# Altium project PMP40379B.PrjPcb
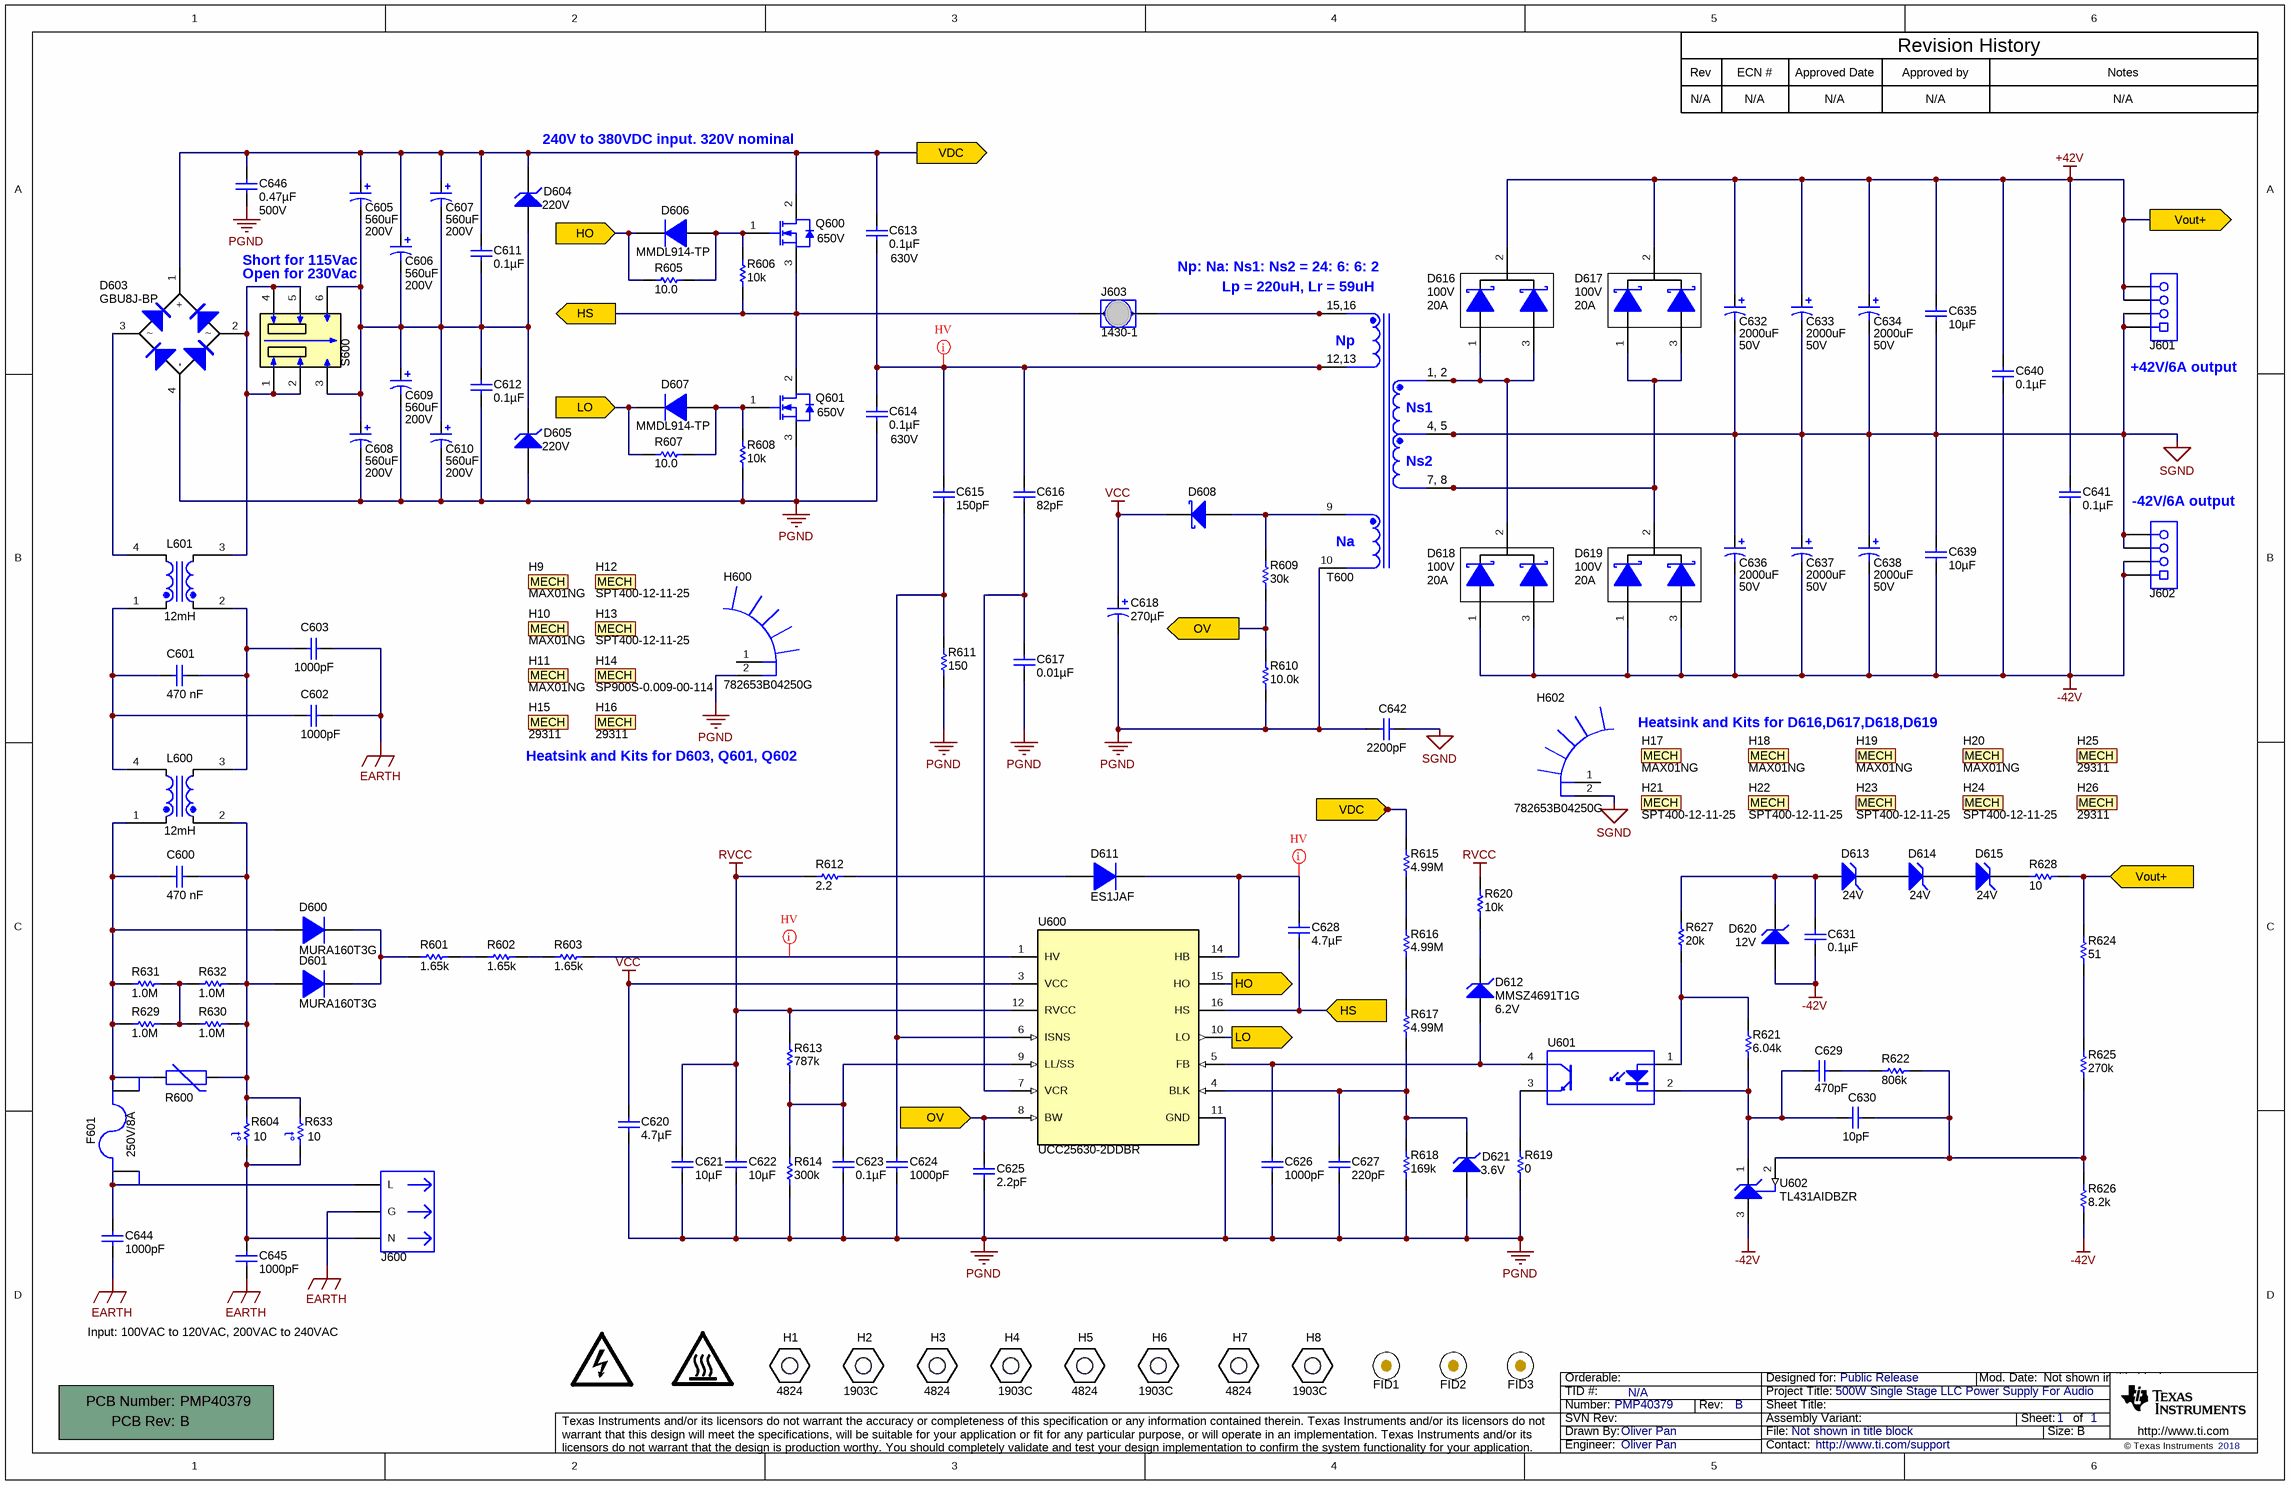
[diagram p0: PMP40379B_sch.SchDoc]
TID: N/A; TechSupport: http://www.ti.com/support; SCH_Rev: B; PRJ_Title: 500W Single Stage LLC Power Supply For Audio; PRJ_Number: PMP40379; PRJ_Engineer: Oliver Pan; PRJ_Customer: Public Release; PCB_Rev: B; PCB_Layout: Oliver Pan; Date: 1222; CopyrightYear: 2018
1 sheet, 146 parts. Net scope: flat (ports and power ports of the same name join across sheets).
Board file: PMP40379B_pcb.PcbDoc

## Sheet PMP40379B_sch.SchDoc
size 431 x 279 mm; Date: Not shown in title block; ApprovedBy: Not shown in title block; CheckedBy: Not shown in title block; Author: Not shown in title block; CompanyName: Not shown in title block; DrawnBy: Oliver Pan; Engineer: Not shown in title block; Organization: Not shown in title block; Address1: Not shown in title block; Address2: Not shown in title block; Address3: Not shown in title block; Address4: Not shown in title block; DocumentNumber: 1; Revision: Use project parameter SCH_Rev; SheetNumber: 1; SheetTotal: 1; PageSetup: Record=PageOptions¦CenterHorizontal=True¦CenterVertical=True¦PrintScale=1.00¦XCorrection=1.00¦YCorrection=1.00¦PrintKind=0¦BorderSize=5000000¦LeftOffset=0¦BottomOffset=0¦Orientation=2¦PaperLength=1000¦PaperWidth=1000¦Scale=100¦PaperSource=15¦PrintQuality=600¦MediaType=1¦DitherType=10¦PaperKind=Letter¦PrintScaleMode=1

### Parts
!PCB600  Printed Circuit Board  (value not drawn)  (mechanical)
C600  value 470 nF  [WCAP-FTX2_18x8x14_CS]  (hidden comment: 275V AC, 470 nF)
C601  value 470 nF  [WCAP-FTX2_18x8x14_CS]  (hidden comment: 275V AC, 470 nF)
C602  ValueDisplayed: 1000pF  [CD45_700x600x1100]  (hidden comment: CD45-E2GA102M-NKA)
C603  ValueDisplayed: 1000pF  [CD45_700x600x1100]  (hidden comment: CD45-E2GA102M-NKA)
C605  value 560uF  Value2: 200V  [CAPPR7.5-18x40]  (hidden comment: EPAG201ELL561MM45S)
C606  value 560uF  Value2: 200V  [CAPPR7.5-18x40]  (hidden comment: EPAG201ELL561MM45S)
C607  value 560uF  Value2: 200V  [CAPPR7.5-18x40]  (hidden comment: EPAG201ELL561MM45S)
C608  value 560uF  Value2: 200V  [CAPPR7.5-18x40]  (hidden comment: EPAG201ELL561MM45S)
C609  value 560uF  Value2: 200V  [CAPPR7.5-18x40]  (hidden comment: EPAG201ELL561MM45S)
C610  value 560uF  Value2: 200V  [CAPPR7.5-18x40]  (hidden comment: EPAG201ELL561MM45S)
C611  ValueDisplayed: 0.1µF  [1206_180]  (hidden comment: GRM31CR72E104KW03L)
C612  ValueDisplayed: 0.1µF  [1206_180]  (hidden comment: GRM31CR72E104KW03L)
C613  ValueDisplayed: 0.1µF  Value2: 630V  [CAPRR1500W80L1800T770H1210]  (hidden comment: ECW-F6104JL)
C614  ValueDisplayed: 0.1µF  Value2: 630V  [CAPRR1500W80L1800T770H1210]  (hidden comment: ECW-F6104JL)
C615  ValueDisplayed: 150pF  [1206]  (hidden comment: GRM31A5C2J151JW01D)
C616  ValueDisplayed: 82pF  [1206]  (hidden comment: GRM31A5C2J820JW01D)
C617  ValueDisplayed: 0.01µF  [0603]  (hidden comment: GRM188R71C103KA01D)
C618  ValueDisplayed: 270µF  [Chemi-Con_800x2000]  (hidden comment: EKZE350ELL271MH20D)
C620  ValueDisplayed: 4.7µF  [1206]  (hidden comment: C3216X7R1V475K085AC)
C621  ValueDisplayed: 10µF  [0805]  (hidden comment: GRM21BC71C106KE11L)
C622  ValueDisplayed: 10µF  [0805]  (hidden comment: GRM21BC71C106KE11L)
C623  ValueDisplayed: 0.1µF  [0603]  (hidden comment: C1608X7R1H104K080AA)
C624  ValueDisplayed: 1000pF  [0603]  (hidden comment: GRM1885C1H102JA01D)
C625  ValueDisplayed: 2.2pF  [0603]  (hidden comment: 06035A2R2CAT2A)
C626  ValueDisplayed: 1000pF  [0603]  (hidden comment: GRM1885C2A102JA01D)
C627  ValueDisplayed: 220pF  [0603]  (hidden comment: GRM188R71H221KA01D)
C628  ValueDisplayed: 4.7µF  [1206_180]  (hidden comment: GRM31CR71C475KA01L)
C629  ValueDisplayed: 470pF  [0603]  (hidden comment: C0603X471K5RACTU)
C630  ValueDisplayed: 10pF  [0603]  (hidden comment: 06035A100JAT2A)
C631  ValueDisplayed: 0.1µF  [0603]  (hidden comment: 06033C104JAT2A)
C632  value 2000uF  Value2: 50V  [Chemi-Con_1450x2000]  (hidden comment: EGXF500ELL202MU40S)
C633  value 2000uF  Value2: 50V  [Chemi-Con_1450x2000]  (hidden comment: EGXF500ELL202MU40S)
C634  value 2000uF  Value2: 50V  [Chemi-Con_1450x2000]  (hidden comment: EGXF500ELL202MU40S)
C635  ValueDisplayed: 10µF  [1206_180]  (hidden comment: C3216X5R1H106K160AB)
C636  value 2000uF  Value2: 50V  [Chemi-Con_1450x2000]  (hidden comment: EGXF500ELL202MU40S)
C637  value 2000uF  Value2: 50V  [Chemi-Con_1450x2000]  (hidden comment: EGXF500ELL202MU40S)
C638  value 2000uF  Value2: 50V  [Chemi-Con_1450x2000]  (hidden comment: EGXF500ELL202MU40S)
C639  ValueDisplayed: 10µF  [1206_180]  (hidden comment: C3216X5R1H106K160AB)
C640  ValueDisplayed: 0.1µF  [1206]  (hidden comment: 12061C104JAT2A)
C641  ValueDisplayed: 0.1µF  [1206]  (hidden comment: 12061C104JAT2A)
C642  ValueDisplayed: 2200pF  [AY2_950x500_Straight]  (hidden comment: AY2222M35Y5US63L7)
C644  ValueDisplayed: 1000pF  [CD45_700x600x1100]  (hidden comment: CD45-E2GA102M-NKA)
C645  ValueDisplayed: 1000pF  [CD45_700x600x1100]  (hidden comment: CD45-E2GA102M-NKA)
C646  ValueDisplayed: 0.47µF  Value2: 500V  [1812_254]  (hidden comment: 1812Y5000474KXTWS2)
D600  MURA160T3G  [SMA]
D601  MURA160T3G  [SMA]
D603  GBU8J-BP  [GBU]
D604  value 220V  [SMB]  (hidden comment: P6SMB220A-E3/52)
D605  value 220V  [SMB]  (hidden comment: P6SMB220A-E3/52)
D606  MMDL914-TP  [SOD-323]
D607  MMDL914-TP  [SOD-323]
D608  STPS160UY  [SMB]  (value not drawn)
D611  ES1JAF  [SMAF]
D612  MMSZ4691T1G  value 6.2V  [SOD-123]
D613  value 24V  [SOD-123]  (hidden comment: MMSZ5252B-7-F)
D614  value 24V  [SOD-123]  (hidden comment: MMSZ5252B-7-F)
D615  value 24V  [SOD-123]  (hidden comment: MMSZ5252B-7-F)
D616  value 100V  Value1: 20A  [TO-220AB]  (hidden comment: STPS41H100CTY)
D617  value 100V  Value1: 20A  [TO-220AB]  (hidden comment: STPS41H100CTY)
D618  value 100V  Value1: 20A  [TO-220AB]  (hidden comment: STPS41H100CTY)
D619  value 100V  Value1: 20A  [TO-220AB]  (hidden comment: STPS41H100CTY)
D620  value 12V  [SOD-123]  (hidden comment: MMSZ5242B-7-F)
D621  value 3.6V  [SOD-123]  (hidden comment: MMSZ5227B-7-F)
F601  value 250V/8A  (hidden comment: 5HF 8-R)  (mechanical)
FID1  Fiducial  [Fiducial10-20]  (value not drawn)
FID2  Fiducial  [Fiducial10-20]  (value not drawn)
FID3  Fiducial  [Fiducial10-20]  (value not drawn)
H1  4824  [KEYSTONE_4824]
H2  1903C  [KEYSTONE_1903C]
H3  4824  [KEYSTONE_4824]
H4  1903C  [KEYSTONE_1903C]
H5  4824  [KEYSTONE_4824]
H6  1903C  [KEYSTONE_1903C]
H7  4824  [KEYSTONE_4824]
H8  1903C  [KEYSTONE_1903C]
H9  MAX01NG  (mechanical)
H10  MAX01NG  (mechanical)
H11  MAX01NG  (mechanical)
H12  SPT400-12-11-25  (mechanical)
H13  SPT400-12-11-25  (mechanical)
H14  SP900S-0.009-00-114  (mechanical)
H15  29311  (mechanical)
H16  29311  (mechanical)
H17  MAX01NG  (mechanical)
H18  MAX01NG  (mechanical)
H19  MAX01NG  (mechanical)
H20  MAX01NG  (mechanical)
H21  SPT400-12-11-25  (mechanical)
H22  SPT400-12-11-25  (mechanical)
H23  SPT400-12-11-25  (mechanical)
H24  SPT400-12-11-25  (mechanical)
H25  29311  (mechanical)
H26  29311  (mechanical)
H600  782653B04250G  [HEATSINK_782653B04250G]
H602  782653B04250G  [HEATSINK_782653B04250G]
J600  703W-00/54  [CONN_QUALTEK-703W-0054]  (value not drawn)
J601  ED120/4DS  [On-Shore_ED120_4DS]  (value not drawn)
J602  ED120/4DS  [On-Shore_ED120_4DS]  (value not drawn)
J603  1430-1  [Keystone_1430-1]
L600  value 12mH  [WE-CMBNC_Type XL_7448051012]  (hidden comment: 7448051012)
L601  value 12mH  [WE-CMBNC_Type XL_7448051012]  (hidden comment: 7448051012)
Logo1  DANGER HIGH VOLTAGE  [IEC_HighVoltage_Medium]  (value not drawn)  (no BOM)
Logo2  CAUTION HOT SURFACE  [IEC_HotSurface_Small]  (value not drawn)  (no BOM)
Q600  value 650V  [TO-220FP]  (hidden comment: IPA65R190CFD)
Q601  value 650V  [TO-220FP]  (hidden comment: IPA65R190CFD)
R600  S10K275E2  [VAR_S10K275E2]  (value not drawn)
R601  ValueDisplayed: 1.65k  [1206]  (hidden comment: CRCW12061K65FKEA)
R602  ValueDisplayed: 1.65k  [1206]  (hidden comment: CRCW12061K65FKEA)
R603  ValueDisplayed: 1.65k  [1206]  (hidden comment: CRCW12061K65FKEA)
R604  value 10  [SPNL20]  (hidden comment: B57364S0100M051)
R605  ValueDisplayed: 10.0  [0603]  (hidden comment: CRCW060310R0FKEA)
R606  ValueDisplayed: 10k  [0603]  (hidden comment: RC0603JR-0710KL)
R607  ValueDisplayed: 10.0  [0603]  (hidden comment: CRCW060310R0FKEA)
R608  ValueDisplayed: 10k  [0603]  (hidden comment: RC0603JR-0710KL)
R609  ValueDisplayed: 30k  [0603]  (hidden comment: CRCW060330K0JNEA)
R610  ValueDisplayed: 10.0k  [0603]  (hidden comment: CRCW060310K0FKEA)
R611  ValueDisplayed: 150  [1206]  (hidden comment: RC1206FR-07150RL)
R612  ValueDisplayed: 2.2  [0603]  (hidden comment: CRCW06032R20JNEA)
R613  ValueDisplayed: 787k  [0603]  (hidden comment: CRCW0603787KFKEA)
R614  ValueDisplayed: 300k  [0603]  (hidden comment: CRCW0603300KJNEA)
R615  ValueDisplayed: 4.99M  [1206]  (hidden comment: CRCW12064M99FKEA)
R616  ValueDisplayed: 4.99M  [1206]  (hidden comment: CRCW12064M99FKEA)
R617  ValueDisplayed: 4.99M  [1206]  (hidden comment: CRCW12064M99FKEA)
R618  ValueDisplayed: 169k  [0603]  (hidden comment: RC0603FR-07169KL)
R619  ValueDisplayed: 0  [0603]  (hidden comment: CRCW06030000Z0EA)
R620  ValueDisplayed: 10k  [0603]  (hidden comment: CRCW060310K0JNEA)
R621  ValueDisplayed: 6.04k  [0603]  (hidden comment: CRCW06036K04FKEA)
R622  ValueDisplayed: 806k  [0603]  (hidden comment: CRCW0603806KFKEA)
R624  ValueDisplayed: 51  [0603]  (hidden comment: CRCW060351R0JNEA)
R625  ValueDisplayed: 270k  [0603]  (hidden comment: CRCW0603270KJNEA)
R626  ValueDisplayed: 8.2k  [0603]  (hidden comment: CRCW06038K20JNEA)
R627  ValueDisplayed: 20k  [0603]  (hidden comment: CRCW060320K0JNEA)
R628  ValueDisplayed: 10  [0603]  (hidden comment: CRCW060310R0JNEA)
R629  ValueDisplayed: 1.0M  [1206]  (hidden comment: CRCW12061M00JNEA)
R630  ValueDisplayed: 1.0M  [1206]  (hidden comment: CRCW12061M00JNEA)
R631  ValueDisplayed: 1.0M  [1206]  (hidden comment: CRCW12061M00JNEA)
R632  ValueDisplayed: 1.0M  [1206]  (hidden comment: CRCW12061M00JNEA)
R633  value 10  [SPNL20]  (hidden comment: B57364S0100M051)
S600  V80212MS02Q  [SW_V80212MS02Q]  (value not drawn)
T600  750343844  [WE-LLCR_ETD44]  (value not drawn)
U600  UCC25630-2DDBR  [DDB0014A]
U601  VO618A  [DIP-4]  (value not drawn)
U602  TL431AIDBZR  [DBZ0003A_N]
XF1  0751.0052  [SCHURTER_0751_0052]  (value not drawn)
XF2  0751.0052  [SCHURTER_0751_0052]  (value not drawn)

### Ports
HO, HS, LO, OV, VDC, Vout+

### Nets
+42V: C632.1(+) C633.1(+) C634.1(+) C635.1 C640.1 C641.1 D616.2(K) D617.2(K) J601.3 J601.4 R624.2 R628.1 ; port Vout+
-42V: C631.2 C636.2(-) C637.2(-) C638.2(-) C639.2 C640.2 C641.2 D618.1(A) D618.3(A) D619.1(A) D619.3(A) D620.2(A) J602.1 J602.2 R626.1 U602.3(ANODE)
EARTH: C602.2 C603.2 C644.2 C645.1 J600.3(G)
PGND: C608.2(-) C609.2(-) C610.2(-) C612.2 C614.2 C617.2 C618.2(-) C620.1 C621.2 C622.2 C623.2 C624.1 C625.2 C626.2 C627.2 C642.2 C646.2 D603.4(-) D605.2(A) D621.2(A) H600.2 Q601.3(S) R608.1 R610.1 R611.1 R614.1 R618.1 R619.1 T600.10 U600.11(GND)
RVCC: C621.1 C622.1 R612.1 R613.2 R620.2 U600.12(RVCC)
SGND: C632.2(-) C633.2(-) C634.2(-) C635.2 C636.1(+) C637.1(+) C638.1(+) C639.1 C642.1 H602.2 J601.1 J601.2 J602.3 J602.4 T600.4 T600.5
VCC: C618.1(+) C620.2 D608.1(K) U600.3(VCC)
HO: D606.1(K) R605.1 U600.15(HO) ; port HO
HS: C628.2 J603.1 Q600.3(S) Q601.2(D) R606.1 U600.16(HS) ; port HS
LO: D607.1(K) R607.1 U600.10(LO) ; port LO
OV: C625.1 R609.1 R610.2 U600.8(BW) ; port OV
VDC: C605.1(+) C606.1(+) C607.1(+) C611.1 C613.1 C646.1 D603.1(+) D604.1(K) Q600.2(D) R615.2 ; port VDC
NetC600_1: C600.1 D600.2(A) L600.1 R600.1 R629.2 R631.2 XF2.1 XF2.2
NetC600_2: C600.2 D601.2(A) L600.2 R600.2 R604.1 R630.1 R632.1 R633.1
NetC601_1: C601.1 C602.1 L600.4 L601.1
NetC601_2: C601.2 C603.1 L600.3 L601.2
NetC605_2: C605.2(-) C606.2(-) C607.2(-) C608.1(+) C609.1(+) C610.1(+) C611.2 C612.1 D604.2(A) D605.1(K) S600.3 S600.6
NetC613_2: C613.2 C614.1 C615.1 C616.1 T600.12 T600.13
NetC615_2: C615.2 C624.2 R611.2 U600.6(ISNS)
NetC616_2: C616.2 C617.1 U600.7(VCR)
NetC623_1: C623.1 R613.1 R614.2 U600.9(LL/SS)
NetC626_1: C626.1 D612.2(A) U600.5(FB) U601.4(C)
NetC627_1: C627.1 D621.1(K) R617.1 R618.2 U600.4(BLK)
NetC628_1: C628.1 D611.1(K) U600.14(HB)
NetC629_1: C629.1 R622.1
NetC629_2: C629.2 C630.2 R621.1 U601.2(K) U602.1(CATHODE)
NetC630_1: C630.1 R622.2 R625.1 R626.2 U602.2(REF)
NetC631_1: C631.1 D613.2(A) D620.1(K) R627.2
NetC644_1: C644.1 J600.1(L) XF1.1 XF1.2
NetC645_2: C645.2 J600.2(N) R604.2 R633.2
NetD600_1: D600.1(K) D601.1(K) R601.2
NetD603_2: D603.2 L601.3 S600.1 S600.2(C) S600.4 S600.5(C)
NetD603_3: D603.3 L601.4
NetD606_2: D606.2(A) Q600.1(G) R605.2 R606.2
NetD607_2: D607.2(A) Q601.1(G) R607.2 R608.2
NetD608_2: D608.2(A) R609.2 T600.9
NetD611_2: D611.2(A) R612.2
NetD612_1: D612.1(K) R620.1
NetD613_1: D613.1(K) D614.2(A)
NetD614_1: D614.1(K) D615.2(A)
NetD615_1: D615.1(K) R628.2
NetD616_1: D616.1(A) D616.3(A) D618.2(K) T600.1 T600.2
NetD617_1: D617.1(A) D617.3(A) D619.2(K) T600.7 T600.8
NetJ603_2: J603.2 T600.15 T600.16
NetR601_1: R601.1 R602.2
NetR602_1: R602.1 R603.2
NetR603_1: R603.1 U600.1(HV)
NetR615_1: R615.1 R616.2
NetR616_1: R616.1 R617.2
NetR619_2: R619.2 U601.3(E)
NetR621_2: R621.2 R627.1 U601.1(A)
NetR624_1: R624.1 R625.2
NetR629_1: R629.1 R630.2 R631.1 R632.2

Not connected (* = marked no-connect by the designer): H600 1; H602 1

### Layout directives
net class HV; rule Clearance Constraint [Clearance = 1.6mm]: NetC613_2
net class HV; rule Clearance Constraint [Clearance = 2.5mm]: NetC628_1
net class HV; rule Clearance Constraint [Clearance = 2mm]: NetR603_1

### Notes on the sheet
- Rev
- N/A
- ECN #
- Approved Date
- Approved by
- Revision History
- Notes
- 240V to 380VDC input. 320V nominal
- VDC start: 232 V
  VDC stop: 210 V
  VAC start: 82 V
  VAC stop: 75 V
- Short for 115Vac
- Open for 230Vac
- Np: Na: Ns1: Ns2 = 24: 6: 6: 2
- (near T600) Lp = 220uH, Lr = 59uH
- (near T600) Np
- (near J601) +42V/6A output
- (near T600) Ns1
- (near T600) Ns2
- (near J602) -42V/6A output
- (near T600) Na
- Heatsink and Kits for D603, Q601, Q602
- (near R610) Vout OVP: 45V
- Heatsink and Kits for D616,D617,D618,D619
- Input: 100VAC to 120VAC, 200VAC to 240VAC

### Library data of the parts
!PCB600 = PCB: Manufacturer: Any; PartNumber: PMP40379; SymbolCreator: a0412235
C600 C601 = 890324025039CS: WCAP-FTX2 Film Capacitors, 18x8x14mm, 275V AC, 470 nF; Manufacturer: Wurth Electronics; Rated Voltage: 275V AC
C602 C603 C644 C645 = CD45-E2GA102M-NKA: CAP, CERM, 1000 pF, X1 440 VAC/Y1 400 VAC, +/- 20%, E, D7xT6mm; Manufacturer: TDK; Polarized: N; CompType: Capacitor; Value: 1000pF; U/M: EA; Cap_F: 0.000000001; Tolerance_%: 20; TaMin_C: -25; TaMax_C: 125; Cap_Case: 7x6x11mm; SizeArea_mm2: 63.9; SizeAreaWB_mm2: 101.2; SizeX_mm: 10.65; SizeY_mm: 6; SizeZ_mm: 11; AEC Category: Q200; AC_Safety: X1Y1; VAC_X: 440; VAC_Y: 400
C605-C610 = Capacitor_Polarized: CAP ALUM 560UF 20% 200V RADIAL; Manufacturer: United Chemi-Con; Lifetime @ Temp.: 2000 Hrs @ 105°C; Polarization: Polar
C611 C612 = GRM31CR72E104KW03L: CAP, CERM, 0.1 µF, 250 V,+/- 10%, X7R, 1206; Manufacturer: MuRata; Polarized: N; CompType: Capacitor; Value: 0.1uF; U/M: EA; Cap_F: 0.0000001; Tolerance_%: 10; VDC_V: 250; Value2: 250V; TaMin_C: -55; TaMax_C: 125; Cap_Case: 1206; SizeAreaWB_mm2: 10.92; SizeArea_mm2: 5.12; SizeX_mm: 3.2; SizeY_mm: 1.6; SizeZ_mm: 1.8; AEC Category: Q200; Green_Lifecycle: Active; Green_REACh: Passed
C613 C614 = ECW-F6104JL: CAP, Film, 0.1 µF, 630 V,+/- 5%, TH; Manufacturer: Panasonic; Value: 0.1uF; Polarized: N; CompType: Capacitor; U/M: EA; Cap_F: 0.0000001; Tolerance_%: 5; VDC_V: 630; TaMin_C: -40; TaMax_C: 105; Cap_Case: Radial 18x7.7x13.6; AEC Category: Q200
C615 = GRM31A5C2J151JW01D: CAP, CERM, 150 pF, 630 V,+/- 5%, C0G/NP0, 1206; Manufacturer: MuRata; Polarized: N; CompType: Capacitor; Value: 150pF; U/M: EA; Cap_F: 0.00000000015; Tolerance_%: 5; VDC_V: 630; Value2: 630V; TaMin_C: -55; TaMax_C: 125; AEC Category: Q200; SizeArea_mm2: 5.12; SizeAreaWB_mm2: 10.92; SizeX_mm: 3.2; SizeY_mm: 1.6; SizeZ_mm: 1.35
C616 = GRM31A5C2J820JW01D: CAP, CERM, 82 pF, 630 V,+/- 5%, C0G/NP0, 1206; Manufacturer: MuRata; Tolerance_%: 5; VDC_V: 630; Value: 82pF; Polarized: N; CompType: Capacitor; U/M: EA; Cap_F: 0.000000000082; Value2: 630V; TaMin_C: -55; TaMax_C: 125; SizeArea_mm2: 5.12; SizeAreaWB_mm2: 10.92; SizeX_mm: 3.2; SizeY_mm: 1.6; SizeZ_mm: 1.35; AEC Category: Q200
C617 = GRM188R71C103KA01D: CAP, CERM, 0.01 µF, 16 V,+/- 10%, X7R, 0603; Manufacturer: MuRata; Polarized: N; CompType: Capacitor; Value: 0.01uF; U/M: EA; Cap_F: 0.00000001; Tolerance_%: 10; VDC_V: 16; Value2: 16V; TaMin_C: -55; TaMax_C: 125; SizeArea_mm2: 1.28; SizeAreaWB_mm2: 4.68; SizeX_mm: 1.6; SizeY_mm: 0.8; SizeZ_mm: 1; AEC Category: Q200; Green_Lifecycle: Active; Green_REACh: Passed
C618 = EKZE350ELL271MH20D: CAP, AL, 270 µF, 35 V, +/- 20%, TH; Manufacturer: Chemi-Con; Value: 270uF; Polarized: Y; CompType: Capacitor; U/M: EA; Cap_F: 0.00027; Tolerance_%: 20; VDC_V: 35; Value2: 35V; IRMS_A: 1.25; TaMin_C: -40; TaMax_C: 105; Cap_Case: 8x20; SizeAreaWB_mm2: 100; SizeArea_mm2: 64; SizeX_mm: 8; SizeZ_mm: 21.5; AEC Category: Q200; AEC Qualified: N
C620 = C3216X7R1V475K085AC: CAP, CERM, 4.7 µF, 35 V,+/- 10%, X7R, 1206; Manufacturer: TDK; Polarized: N; CompType: Capacitor; Value: 4.7uF; U/M: EA; Cap_F: 0.0000047; Tolerance_%: 10; ESR_ohm: 0.003785; Value1: 0.003785 ohm; VDC_V: 35; Value2: 35V; IRMS_A: 3.73011; TaMin_C: -55; TaMax_C: 125; AEC Category: Q200; SizeArea_mm2: 5.12; SizeAreaWB_mm2: 10.92; SizeX_mm: 3.2; SizeY_mm: 1.6; SizeZ_mm: 1.35
C621 C622 = GRM21BC71C106KE11L: CAP, CERM, 10 µF, 16 V,+/- 10%, X7S, 0805; Manufacturer: MuRata; Polarized: N; CompType: Capacitor; Value: 10uF; U/M: EA; Cap_F: 0.00001; Tolerance_%: 10; VDC_V: 16; Value2: 16V; TaMin_C: -55; TaMax_C: 125; AEC Category: Q200; SizeArea_mm2: 2.5; SizeAreaWB_mm2: 6.75; SizeX_mm: 2; SizeY_mm: 1.25; SizeZ_mm: 1.45
C623 = C1608X7R1H104K080AA: CAP, CERM, 0.1 µF, 50 V,+/- 10%, X7R, 0603; Manufacturer: TDK; Polarized: N; CompType: Capacitor; Value: 0.1uF; U/M: EA; Cap_F: 0.0000001; Tolerance_%: 10; ESR_ohm: 0.0296; Value1: 0.0296 ohm; VDC_V: 50; Value2: 50V; IRMS_A: 0.97199; TaMin_C: -55; TaMax_C: 125; AEC Category: Q200; SizeArea_mm2: 1.28; SizeAreaWB_mm2: 4.68; SizeX_mm: 1.6; SizeY_mm: 0.8; SizeZ_mm: 1; Green_Lifecycle: NRND; Green_REACh: Passed
C624 = GRM1885C1H102JA01D: CAP, CERM, 1000 pF, 50 V,+/- 5%, C0G/NP0, 0603; Manufacturer: MuRata; Polarized: N; CompType: Capacitor; Value: 1000pF; U/M: EA; Cap_F: 0.000000001; Tolerance_%: 5; VDC_V: 50; Value2: 50V; TaMin_C: -55; TaMax_C: 125; SizeArea_mm2: 1.28; SizeAreaWB_mm2: 4.68; SizeX_mm: 1.6; SizeY_mm: 0.8; SizeZ_mm: 1; AEC Category: Q200; Green_Lifecycle: Active; Green_REACh: Passed
C625 = 06035A2R2CAT2A: CAP, CERM, 2.2 pF, 50 V, +/- 11%, C0G/NP0, 0603; Manufacturer: AVX; Polarized: N; CompType: Capacitor; Value: 2.2pF; U/M: EA; Cap_F: 0.0000000000022; Tolerance_%: 11; ESR_ohm: 1.033; Value1: 1.033 ohm; VDC_V: 50; Value2: 50V; TaMin_C: -55; TaMax_C: 125; SizeArea_mm2: 1.28; SizeAreaWB_mm2: 4.68; SizeX_mm: 1.6; SizeY_mm: 0.8; SizeZ_mm: 1; AEC Category: Q200
C626 = GRM1885C2A102JA01D: CAP, CERM, 1000 pF, 100 V,+/- 5%, C0G/NP0, 0603; Manufacturer: MuRata; Polarized: N; CompType: Capacitor; Value: 1000pF; U/M: EA; Cap_F: 0.000000001; Tolerance_%: 5; VDC_V: 100; Value2: 100V; TaMin_C: -55; TaMax_C: 125; AEC Category: Q200; SizeArea_mm2: 1.28; SizeAreaWB_mm2: 4.68; SizeX_mm: 1.6; SizeY_mm: 0.8; SizeZ_mm: 1; Green_Lifecycle: Active; Green_REACh: Passed
C627 = GRM188R71H221KA01D: CAP, CERM, 220 pF, 50 V, +/- 10%, X7R, 0603; Manufacturer: MuRata; Polarized: N; CompType: Capacitor; Value: 220pF; U/M: EA; Cap_F: 0.00000000022; Tolerance_%: 10; Value1: Unknown; VDC_V: 50; Value2: 50V; TaMin_C: -55; TaMax_C: 125; AEC Category: Q200
C628 = GRM31CR71C475KA01L: CAP, CERM, 4.7 µF, 16 V,+/- 10%, X7R, 1206; Manufacturer: MuRata; Polarized: N; CompType: Capacitor; Value: 4.7uF; U/M: EA; Cap_F: 0.0000047; Tolerance_%: 10; VDC_V: 16; Value2: 16V; TaMin_C: -55; TaMax_C: 125; Cap_Case: 1206; AEC Category: Q200; SizeArea_mm2: 5.12; SizeAreaWB_mm2: 10.92; SizeX_mm: 3.2; SizeY_mm: 1.6; SizeZ_mm: 1.8
C629 = C0603X471K5RACTU: CAP, CERM, 470 pF, 50 V, +/- 10%, X7R, 0603; Manufacturer: Kemet; Polarized: N; CompType: Capacitor; Value: 470pF; U/M: EA; Cap_F: 0.00000000047; Tolerance_%: 10; Value1: Unknown; VDC_V: 50; Value2: 50V; TaMin_C: -55; TaMax_C: 125; SizeArea_mm2: 1.28; SizeAreaWB_mm2: 4.68; SizeX_mm: 1.6; SizeY_mm: 0.8; SizeZ_mm: 1; AEC Category: Q200
C630 = 06035A100JAT2A: CAP, CERM, 10 pF, 50 V, +/- 5%, C0G/NP0, 0603; Manufacturer: AVX; Polarized: N; CompType: Capacitor; Value: 10pF; U/M: EA; Cap_F: 0.00000000001; Tolerance_%: 5; ESR_ohm: 0.403; Value1: 0.403 ohm; VDC_V: 50; Value2: 50V; TaMin_C: -55; TaMax_C: 125; AEC Category: Q200; SizeArea_mm2: 1.28; SizeAreaWB_mm2: 4.68; SizeX_mm: 1.6; SizeY_mm: 0.8; SizeZ_mm: 1
C631 = 06033C104JAT2A: CAP, CERM, 0.1 µF, 25 V, +/- 5%, X7R, 0603; Manufacturer: AVX; CompType: Capacitor; U/M: EA; Cap_F: 0.0000001; Value: 0.1uF; Tolerance_%: 5; ESR_ohm: 0.05; Value1: 0.05 ohm; VDC_V: 25; Value2: 25V; TaMin_C: -55; TaMax_C: 125; Polarized: N; SizeArea_mm2: 1.28; SizeAreaWB_mm2: 4.68; SizeX_mm: 1.6; SizeY_mm: 0.8; SizeZ_mm: 1; AEC Category: Q200
C632-C634 C636-C638 = Capacitor_Polarized: CAP ALUM 2000UF 20% 50V RADIAL; Manufacturer: United Chemi-Con; ESR_Ohm: 20 mOhm @ 100kHz; Lifetime @ Temp.: 3000 Hrs @ 125°C; Polarization: Polar
C635 C639 = C3216X5R1H106K160AB: CAP, CERM, 10 µF, 50 V,+/- 10%, X5R, 1206; Manufacturer: TDK; Polarized: N; CompType: Capacitor; Value: 10uF; U/M: EA; Cap_F: 0.00001; Tolerance_%: 10; Value1: 0.002229 ohm; VDC_V: 50; Value2: 50V; ESR_ohm: 0.002229; IRMS_A: 4.85932; TaMin_C: -55; TaMax_C: 85; Cap_Case: 1206; SizeAreaWB_mm2: 10.92; SizeArea_mm2: 5.12; SizeX_mm: 3.2; SizeY_mm: 1.6; SizeZ_mm: 1.8; AEC Category: Q200; Green_Lifecycle: Active; Green_REACh: Passed
C640 C641 = 12061C104JAT2A: CAP, CERM, 0.1 µF, 100 V,+/- 5%, X7R, 1206; Manufacturer: AVX; Polarized: N; CompType: Capacitor; Value: 0.1uF; U/M: EA; Cap_F: 0.0000001; Tolerance_%: 5; Value1: 0.037 ohm; VDC_V: 100; Value2: 100V; ESR_ohm: 0.037; TaMin_C: -55; TaMax_C: 125; SizeAreaWB_mm2: 10.92; SizeArea_mm2: 5.12; SizeX_mm: 3.2; SizeY_mm: 1.6; SizeZ_mm: 1.35; AEC Category: Q200; Green_Lifecycle: Active; Green_REACh: Passed
C642 = AY2222M35Y5US63L7: CAP, CERM, 2200 pF, 300 V, +/- 20%, Y5U, AEC-Q200 Grade 1, D9.5xT5mm; Manufacturer: Vishay-Bccomponents; Polarized: N; CompType: Capacitor; Value: 2200pF; U/M: EA; Cap_F: 0.0000000022; Tolerance_%: 20; Value1: Unknown; VDC_V: 300; Value2: 300V; TaMin_C: -55; TaMax_C: 125; Cap_Case: 9.5x5mm; SizeArea_mm2: 47.5; SizeAreaWB_mm2: 80.5; SizeX_mm: 9.5; SizeY_mm: 5; SizeZ_mm: 14.5; AEC Category: Q200; AEC Qualified: Y; AEC Grade: 1
C646 = 1812Y5000474KXTWS2: CAP, CERM, 0.47 µF, 500 V,+/- 10%, X7R, 1812; Manufacturer: Knowles Capacitors; Value: 0.47uF; Polarized: N; CompType: Capacitor; U/M: EA; Cap_F: 0.00000047; Tolerance_%: 10; VDC_V: 500; TaMin_C: -55; TaMax_C: 125; Cap_Case: 1812; SizeArea_mm2: 14.4; SizeAreaWB_mm2: 23.1; SizeX_mm: 4.5; SizeY_mm: 3.2; SizeZ_mm: 2.54; AEC Category: Q200; Green_Lifecycle: Not Set; Green_REACh: Incomplete
D600 D601 = MURA160T3G: Diode, Ultrafast, 600V, 1A, SMA; Manufacturer: ON Semiconductor; Value: 1.05V; U/M: EA; Vf_V: 1.05; Io_A: 1; Vr_V: 600; TJmax_C: 175
D603 = GBU8J-BP: Diode, Switching-Bridge, 420 V, 8 A, TH; Manufacturer: Micro Commercial Components; Value: 420V; Value1: 8A; U/M: EA; Vf_V: 1; Value2: 1V; Io_A: 8; Vr_V: 420; TJmax_C: 175; SizeAreaWB_mm2: 130.5915; SizeArea_mm2: 75.6315; SizeX_mm: 22.05; SizeY_mm: 3.43; SizeZ_mm: 21.55; AEC Category: Q101; Green_Lifecycle: Not Set; Green_REACh: Incomplete
D604 D605 = Zener: TVS Diodes - Transient Voltage Suppressors 600W 220V Unidirect; Manufacturer: Vishay Semiconductors; Voltage - Reverse Standoff (Typ): 185V; Voltage - Breakdown (Min): 209V; Voltage - Clamping (Max) @ Ipp: 328V; Direction: Unidirectional; Max Surge Current: 100A; Number of Channels: 1; Max Reverse Leakage Current: 1uA; Test Current: 1mA; Max Breakdown Voltage: 231V; Peak Pulse Current: 1.8A; Element Configuration: Single
D606 D607 = MMDL914-TP: Diode, Switching, 100 V, 0.2 A, SOD-323; Manufacturer: Micro Commercial Components; U/M: EA; Vf_V: 1; Value: 100V; Value1: 0.2A; Value2: 1V; Io_A: 0.2; Vr_V: 100; TJmax_C: 150; SizeAreaWB_mm2: 8.695; SizeArea_mm2: 3.645; SizeX_mm: 2.7; SizeY_mm: 1.35; AEC Category: Q101
D608 = STPS160UY: Diode, Schottky, 60 V, 1 A, AEC-Q101, SMB; Manufacturer: STMicroelectronics; U/M: EA; Vf_V: 0.67; Value: 60V; Value1: 1A; Value2: 0.67V; Io_A: 1; Vr_V: 60; TJmax_C: 150; AEC Category: Q101; AEC Qualified: Y; SizeAreaWB_mm2: 44.156; SizeArea_mm2: 21.336; SizeX_mm: 5.6; SizeY_mm: 3.81; SizeZ_mm: 2.6
D611 = ES1JAF: Diode, Ultrafast, 600 V, 1 A, AEC-Q101, SMAF; Manufacturer: Fairchild Semiconductor; U/M: EA; Vf_V: 1.7; Value: 600V; Value1: 1A; Value2: 1.7V; Io_A: 1; Vr_V: 600; TJmax_C: 150; AEC Category: Q101; AEC Qualified: Y
D612 = MMSZ4691T1G: Diode, Zener, 6.2 V, 500 mW, SOD-123; Manufacturer: ON Semiconductor; SymbolCreator: a0412235; U/M: EA; Power_W: 0.5; Vz_V: 6.2; Value1: 0.5W; RJA_CperW: 340; SizeAreaWB_mm2: 13.095; SizeArea_mm2: 6.545; SizeX_mm: 3.85; SizeY_mm: 1.7; SizeZ_mm: 1.35; AEC Category: Q101
D613-D615 = MMSZ5252B-7-F: Diode, Zener, 24 V, 500 mW, SOD-123; Manufacturer: Diodes Inc.; SymbolCreator: a0412235; U/M: EA; Power_W: 0.5; Vz_V: 24; Value1: 0.5W; RJA_CperW: 350; SizeAreaWB_mm2: 13.095; SizeArea_mm2: 6.545; SizeX_mm: 3.85; SizeY_mm: 1.7; SizeZ_mm: 1.35; AEC Category: Q101
D616-D619 = STPS41H100CTY: Diode, Schottky, 100 V, 20 A, AEC-Q101, TH; Manufacturer: STMicroelectronics; SymbolCreator: a0411947; U/M: EA; Vf_V: 0.8; Value2: 0.8V; Io_A: 20; Vr_V: 100; TJmax_C: 175; SizeAreaWB_mm2: 397.048; SizeArea_mm2: 312.208; SizeX_mm: 30.02; SizeY_mm: 10.4; SizeZ_mm: 4.82; AEC Category: Q101; AEC Qualified: Y
D620 = MMSZ5242B-7-F: Diode, Zener, 12 V, 500 mW, SOD-123; Manufacturer: Diodes Inc.; SymbolCreator: a0412235; U/M: EA; Power_W: 0.5; Vz_V: 12; Value1: 0.5W; RJA_CperW: 350; SizeAreaWB_mm2: 13.095; SizeArea_mm2: 6.545; SizeX_mm: 3.85; SizeY_mm: 1.7; SizeZ_mm: 1.35; AEC Category: Q101
D621 = MMSZ5227B-7-F: Diode, Zener, 3.6 V, 500 mW, SOD-123; Manufacturer: Diodes Inc.; SymbolCreator: a0412235; U/M: EA; Power_W: 0.5; Vz_V: 3.6; Value1: 0.5W; RJA_CperW: 350; SizeAreaWB_mm2: 13.095; SizeArea_mm2: 6.545; SizeX_mm: 3.85; SizeY_mm: 1.7; SizeZ_mm: 1.35; AEC Category: Q101
F601 = FuseMech: FUSE CERAMIC 8A 250VAC 5X20MM; Manufacturer: Bel Fuse Inc.; Fuse Type: Cartridge, Ceramic; Response Time: Fast; Breaking Capacity @ Rated Voltage: 1.5kA; Approvals: CCC, CE, CSA, cURus, PSE, SEMKO
FID1-FID3 = Fiducial: Fiducial mark.  There is nothing to buy or mount.; SymbolCreator: codlsc
H1 H3 H5 H7 = 4824: HEX STANDOFF 6-32 NYLON 1-1/2"; Manufacturer: Keystone; SymbolCreator: a0412235
H2 H4 H6 H8 = 1903C: Standoff, Hex, 0.5"L #6-32 Nylon; Manufacturer: Keystone; SymbolCreator: a0412235
H9-H11 H17-H20 = MechPart: Heatsink clip for TO-220; Manufacturer: Aavid Thermalloy; SymbolCreator: codlsc; CompType: Mechanical; U/M: EA
H12-H14 H21-H24 = MechPart: THERM PAD 25.02X11MM GRAY/GRN; Manufacturer: Bergquist; SymbolCreator: codlsc; CompType: Mechanical; U/M: EA
H15 H16 H25 H26 = MechPart: MACH SCREW PAN HEAD SLOTTED M3; Manufacturer: Keystone Electronics; SymbolCreator: codlsc; CompType: Mechanical; U/M: EA
H600 H602 = 782653B02000G: HEATSINK VERT MAX CLIP, BLACK, 4.25 INCHES; Manufacturer: Aavid; SymbolCreator: a0799628; Green_Lifecycle: Not Set; Green_REACh: Incomplete
J600 = 703W-00/54: AC Receptacle, 10A 250VAC; Manufacturer: Qualtek Electronics Corporation; SymbolCreator: a0799628; CompType: Connector; Green_Lifecycle: Not Set; Green_REACh: Incomplete
J601 J602 = ED120/4DS: Terminal Block, 5.08 mm, 4x1, Brass, TH; Manufacturer: On-Shore Technology; SymbolCreator: a0411947; Pitch_mm: 5.08; Gender: Female; Shrouded: N; Row_Count: 1; Current_A: 15; Voltage_V: 300; Cert_CULUS: Y
J603 = 1430-1: Pin Shorting, Pin Spacing 5.08mm,  TH; Manufacturer: Keystone; SymbolCreator: a0799628; CompType: Jumper Wire; ContactFinish: Gold
L600 L601 = 744825320: CMC 12MH 10A 2LN TH; Manufacturer: WURTH ELEKTRONIK; ValueDisplayed: 20mH
Logo1 = IEC_HighVoltage: IEC 61010-1 High Voltage Warning; SymbolCreator: a0412235
Logo2 = IEC_HotSurface: IEC 61010-1 Hot Surface Warning; SymbolCreator: a0412235
Q600 Q601 = IPA65R190CFD: MOSFET, N-CH, 650 V, 17.5 A, TO-220FP; Manufacturer: Infineon Technologies; Alternate Manufacturer: None; U/M: EA; ChType: N; VdsMax_V: 650; Value1: ? ohm; Value2: 68 nC; QgTyp_nC: 68; Vgs_V: 20; IdsMax_A: 17.5; SizeAreaWB_mm2: 79.3; SizeArea_mm2: 45.9; SizeX_mm: 10.2; SizeY_mm: 4.5; AEC Category: Q101
R600 = S10K275E2: Varistor 275V RMS 10MM Radial, TH; Manufacturer: TDK; SymbolCreator: a0412235; SizeAreaWB_mm2: 103.6; SizeArea_mm2: 64.8; SizeX_mm: 12; SizeY_mm: 5.4; SizeZ_mm: 14.5; Green_Lifecycle: Not Set; Green_REACh: Incomplete
R601-R603 = CRCW12061K65FKEA: RES, 1.65 k, 1%, 0.25 W, 1206; Manufacturer: Vishay-Dale; CompType: Resistor; Value: 1.65k; Res_ohm: 1650; Value_Code: 1k65; Tolerance_%: 1; Power_W: 0.25; Value2: 0.25W; VDC_V: 200; TempCo: 100 ppm/C; EIA_Code: E96; U/M: EA; AEC Category: Q200; SizeArea_mm2: 5.12; SizeX_mm: 3.2; SizeY_mm: 1.6; SizeZ_mm: 1.35
R604 R633 = CMP-0079211-1: ICL 10 OHM 20% 7.5A 21MM; Manufacturer: EPCOS (TDK); Approvals: UL
R605 R607 = CRCW060310R0FKEA: RES, 10.0, 1%, 0.1 W, 0603; Manufacturer: Vishay-Dale; CompType: Resistor; Value: 10.0; Res_ohm: 10; Value_Code: 10R0; Tolerance_%: 1; Power_W: 0.1; Value2: 0.1W; VDC_V: 75; TempCo: 100 ppm/C; SizeArea_mm2: 1.28; SizeX_mm: 1.6; SizeY_mm: 0.8; EIA_Code: E96; U/M: EA; AEC Category: Q200
R606 R608 = RC0603JR-0710KL: RES, 10 k, 5%, 0.1 W, 0603; Manufacturer: Yageo America; CompType: Resistor; Value: 10k; Res_ohm: 10000; Value_Code: 10k0; Tolerance_%: 5; Power_W: 0.1; Value2: 0.1W; VDC_V: 50; TempCo: 100 ppm/C; SizeArea_mm2: 1.28; SizeX_mm: 1.6; SizeY_mm: 0.8; SizeZ_mm: 1; EIA_Code: E24; U/M: EA; AEC Category: Q200; Green_Lifecycle: Active; Green_REACh: Passed
R609 = CRCW060330K0JNEA: RES, 30 k, 5%, 0.1 W, 0603; Manufacturer: Vishay-Dale; CompType: Resistor; Value: 30k; Res_ohm: 30000; Value_Code: 30k0; Tolerance_%: 5; Power_W: 0.1; Value2: 0.1W; VDC_V: 75; TempCo: 200 ppm/C; SizeArea_mm2: 1.28; SizeX_mm: 1.6; SizeY_mm: 0.8; SizeZ_mm: 1; EIA_Code: E24; U/M: EA; AEC Category: Q200; Green_Lifecycle: Active; Green_REACh: Passed
R610 = CRCW060310K0FKEA: RES, 10.0 k, 1%, 0.1 W, 0603; Manufacturer: Vishay-Dale; CompType: Resistor; Value: 10.0k; Res_ohm: 10000; Value_Code: 10k0; Tolerance_%: 1; Power_W: 0.1; Value2: 0.1W; VDC_V: 75; TempCo: 100 ppm/C; EIA_Code: E96; U/M: EA; AEC Category: Q200
R611 = RC1206FR-07150RL: RES, 150, 1%, 0.25 W, 1206; Manufacturer: Yageo America; CompType: Resistor; Value: 150; Value_Code: 150R; Tolerance_%: 1; Power_W: 0.25; Value2: 0.25W; VDC_V: 200; TempCo: 100 ppm/C; SizeArea_mm2: 5.12; SizeX_mm: 3.2; SizeY_mm: 1.6; SizeZ_mm: 1.35; EIA_Code: E96; U/M: EA; AEC Category: Q200; Green_Lifecycle: Active; Green_REACh: Passed
R612 = CRCW06032R20JNEA: RES, 2.2, 5%, 0.1 W, 0603; Manufacturer: Vishay-Dale; CompType: Resistor; Value: 2.2; Value_Code: 2R20; Tolerance_%: 5; Power_W: 0.1; Value2: 0.1W; VDC_V: 75; TempCo: 200 ppm/C; EIA_Code: E24; U/M: EA; SizeArea_mm2: 1.28; SizeX_mm: 1.6; SizeY_mm: 0.8; SizeZ_mm: 1; AEC Category: Q200; Green_Lifecycle: Active; Green_REACh: Passed
R613 = CRCW0603787KFKEA: RES, 787 k, 1%, 0.1 W, 0603; Manufacturer: Vishay-Dale; CompType: Resistor; Value: 787k; Res_ohm: 787000; Tolerance_%: 1; Power_W: 0.1; Value2: 0.1W; VDC_V: 75; TempCo: 100 ppm/C; SizeArea_mm2: 1.28; SizeX_mm: 1.6; SizeY_mm: 0.8; EIA_Code: E96; U/M: EA; AEC Category: Q200
R614 = CRCW0603300KJNEA: RES, 300 k, 5%, 0.1 W, 0603; Manufacturer: Vishay-Dale; CompType: Resistor; Value: 300k; Res_ohm: 300000; Tolerance_%: 5; Power_W: 0.1; Value2: 0.1W; VDC_V: 75; TempCo: 200 ppm/C; SizeArea_mm2: 1.28; SizeX_mm: 1.6; SizeY_mm: 0.8; SizeZ_mm: 1; EIA_Code: E24; U/M: EA; AEC Category: Q200; Green_Lifecycle: Active; Green_REACh: Passed
R615-R617 = CRCW12064M99FKEA: RES, 4.99 M, 1%, 0.25 W, 1206; Manufacturer: Vishay-Dale; CompType: Resistor; Value: 4.99Meg; Res_ohm: 4990000; Value_Code: 4M99; Tolerance_%: 1; Power_W: 0.25; Value2: 0.25W; VDC_V: 200; TempCo: 100 ppm/C; EIA_Code: E96; U/M: EA; AEC Category: Q200; SizeArea_mm2: 5.12; SizeX_mm: 3.2; SizeY_mm: 1.6; SizeZ_mm: 1.35
R618 = RC0603FR-07169KL: RES, 169 k, 1%, 0.1 W, 0603; Manufacturer: Yageo America; CompType: Resistor; Value: 169k; Res_ohm: 169000; Tolerance_%: 1; Power_W: 0.1; Value2: 0.1W; VDC_V: 150; TempCo: 200 ppm/C; SizeArea_mm2: 1.28; SizeX_mm: 1.6; SizeY_mm: 0.8; EIA_Code: E96; U/M: EA; AEC Category: Q200; Green_Lifecycle: Active; Green_REACh: Passed
R619 = CRCW06030000Z0EA: RES, 0, 5%, 0.1 W, 0603; Manufacturer: Vishay-Dale; CompType: Resistor; Value: 0; Value_Code: 0000; Tolerance_%: 5; Power_W: 0.1; Value2: 0.1W; VDC_V: 75; TempCo: 200 ppm/C; SizeArea_mm2: 1.28; SizeX_mm: 1.6; SizeY_mm: 0.8; SizeZ_mm: 1; EIA_Code: E24; U/M: EA; AEC Category: Q200
R620 = CRCW060310K0JNEA: RES, 10 k, 5%, 0.1 W, 0603; Manufacturer: Vishay-Dale; CompType: Resistor; Value: 10k; Res_ohm: 10000; Value_Code: 10k0; Tolerance_%: 5; Power_W: 0.1; Value2: 0.1W; VDC_V: 75; TempCo: 200 ppm/C; SizeArea_mm2: 1.28; SizeX_mm: 1.6; SizeY_mm: 0.8; SizeZ_mm: 1; EIA_Code: E24; U/M: EA; AEC Category: Q200; Green_Lifecycle: Active; Green_REACh: Passed
R621 = CRCW06036K04FKEA: RES, 6.04 k, 1%, 0.1 W, 0603; Manufacturer: Vishay-Dale; CompType: Resistor; Value: 6.04k; Res_ohm: 6040; Value_Code: 6k04; Tolerance_%: 1; Power_W: 0.1; Value2: 0.1W; VDC_V: 75; TempCo: 100 ppm/C; EIA_Code: E96; U/M: EA; AEC Category: Q200
R622 = CRCW0603806KFKEA: RES, 806 k, 1%, 0.1 W, 0603; Manufacturer: Vishay-Dale; CompType: Resistor; Value: 806k; Res_ohm: 806000; Tolerance_%: 1; Power_W: 0.1; Value2: 0.1W; VDC_V: 75; TempCo: 100 ppm/C; EIA_Code: E96; U/M: EA; AEC Category: Q200; SizeArea_mm2: 1.28; SizeX_mm: 1.6; SizeY_mm: 0.8
R624 = CRCW060351R0JNEA: RES, 51, 5%, 0.1 W, 0603; Manufacturer: Vishay-Dale; CompType: Resistor; Value: 51; Value_Code: 51R0; Tolerance_%: 5; Power_W: 0.1; Value2: 0.1W; VDC_V: 75; TempCo: 200 ppm/C; EIA_Code: E24; U/M: EA; AEC Category: Q200; SizeArea_mm2: 1.28; SizeX_mm: 1.6; SizeY_mm: 0.8; SizeZ_mm: 1; Green_Lifecycle: Active; Green_REACh: Passed
R625 = CRCW0603270KJNEA: RES, 270 k, 5%, 0.1 W, 0603; Manufacturer: Vishay-Dale; CompType: Resistor; Value: 270k; Res_ohm: 270000; Tolerance_%: 5; Power_W: 0.1; Value2: 0.1W; VDC_V: 75; TempCo: 200 ppm/C; EIA_Code: E24; U/M: EA; AEC Category: Q200; SizeArea_mm2: 1.28; SizeX_mm: 1.6; SizeY_mm: 0.8; SizeZ_mm: 1
R626 = CRCW06038K20JNEA: RES, 8.2 k, 5%, 0.1 W, 0603; Manufacturer: Vishay-Dale; CompType: Resistor; Value: 8.2k; Res_ohm: 8200; Value_Code: 8k20; Tolerance_%: 5; Power_W: 0.1; Value2: 0.1W; VDC_V: 75; TempCo: 200 ppm/C; SizeArea_mm2: 1.28; SizeX_mm: 1.6; SizeY_mm: 0.8; SizeZ_mm: 1; EIA_Code: E24; U/M: EA; AEC Category: Q200; Green_Lifecycle: Active; Green_REACh: Passed
R627 = CRCW060320K0JNEA: RES, 20 k, 5%, 0.1 W, 0603; Manufacturer: Vishay-Dale; CompType: Resistor; Value: 20k; Res_ohm: 20000; Value_Code: 20k0; Tolerance_%: 5; Power_W: 0.1; Value2: 0.1W; VDC_V: 75; TempCo: 200 ppm/C; EIA_Code: E24; U/M: EA; AEC Category: Q200; SizeArea_mm2: 1.28; SizeX_mm: 1.6; SizeY_mm: 0.8; SizeZ_mm: 1; Green_Lifecycle: Active; Green_REACh: Passed
R628 = CRCW060310R0JNEA: RES, 10, 5%, 0.1 W, 0603; Manufacturer: Vishay-Dale; CompType: Resistor; Value: 10; Value_Code: 10R0; Tolerance_%: 5; Power_W: 0.1; Value2: 0.1W; VDC_V: 75; TempCo: 200 ppm/C; EIA_Code: E24; U/M: EA; AEC Category: Q200; SizeArea_mm2: 1.28; SizeX_mm: 1.6; SizeY_mm: 0.8; SizeZ_mm: 1; Green_Lifecycle: Active; Green_REACh: Passed
R629-R632 = CRCW12061M00JNEA: RES, 1.0 M, 5%, 0.25 W, 1206; Manufacturer: Vishay-Dale; CompType: Resistor; Value: 1.0Meg; Res_ohm: 1000000; Value_Code: 1M00; Tolerance_%: 5; Power_W: 0.25; Value2: 0.25W; VDC_V: 200; TempCo: 200 ppm/C; EIA_Code: E24; U/M: EA; AEC Category: Q200; SizeArea_mm2: 5.12; SizeX_mm: 3.2; SizeY_mm: 1.6; SizeZ_mm: 1.35; Green_Lifecycle: Active; Green_REACh: Passed
S600 = CMP-0079208-1: Switch, Slide, DPDT, On-On, 10 A, 125 VAC, 30 VDC, TH; Manufacturer: C&K Components; SizeAreaWB_mm2: 521.7969; SizeArea_mm2: 432.3969; SizeZ_mm: 15.75; SizeY_mm: 26.19; VDC_V: 30V; CurrentRating_mA: 10kA; PositionCount: 2; SizeX_mm: 16.51
T600 = EE44: Transformer, 220uH, 16-pin, TH, Vertical; Manufacturer: Wurth Elektronik; SymbolVersion: Rev03; SymbolCreator: Altium
U600 = CMP-0077205-3: LLC Resonant Controller With High Voltage Start Up Enabling Low Standby Power, DDB0014A (SOIC-14); Alternate PartNumber: UCC25630-2DDBT; Alternate Manufacturer: Texas Instruments; SizeAreaWB_mm2: 95.2; SizeZ_mm: 1.75; SizeX_mm: 6.0; SizeY_mm: 9.9; SizeArea_mm2: 59.4; CompType: IC; AEC Category: Q200; AEC Qualified: N; Rating: Catalog
U601 = VO618A: Optocoupler, 5.3 kV, 50-600% CTR, TH; Manufacturer: Vishay-Semiconductor; CTR (Min): 50%; CTR (Max): 600%; Voltage_Isolation_Vrms: 5300V; SizeAreaWB_mm2: 71.064; SizeArea_mm2: 40.304; SizeX_mm: 8.8; SizeY_mm: 4.58; SizeZ_mm: 5
U602 = TL431AIDBZR: Adjustable Precision Shunt Regulator, 34 ppm / degC, 100 mA, -40 to 85 degC, 3-pin SOT-23 (DBZ), Green (RoHS & no Sb/Br); Manufacturer: Texas Instruments; Alternate PartNumber: Equivalent; Initial Accuracy @ 25/deg C(%): 1; Iout/Iz(Max)(mA): 100; Min Iz for Regulation(uA): 600; Rating: Catalog; SubFamily: Shunt Voltage Reference; Temp Coeff(Max)(ppm/ degree C): 92; Temp Coeff(Typ)(ppm/ degree C): 34; VO Adj(Max)(V): 36; VO Adj(Min)(V): 2.495
XF1 XF2 = 0751.0052: FUSE CLIP CART 250V 6.3A, Single End; Manufacturer: Schurter; SymbolCreator: a0411947; CompType: Fuse Holder

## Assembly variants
001: not fitted C630 C640 C641 D621 R613 R620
